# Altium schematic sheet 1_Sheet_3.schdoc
size 497 x 243 mm; Name: A_A4; Symbol: A_A4; Device: A_A4; @Project Name: RM_超级电容控制板; REV: 3.4; Date: 2023-02-08; Sheet: 3/3; Draw By: PKKKK; Company: QiDian; Convert to PCB: yes; Add into BOM: yes
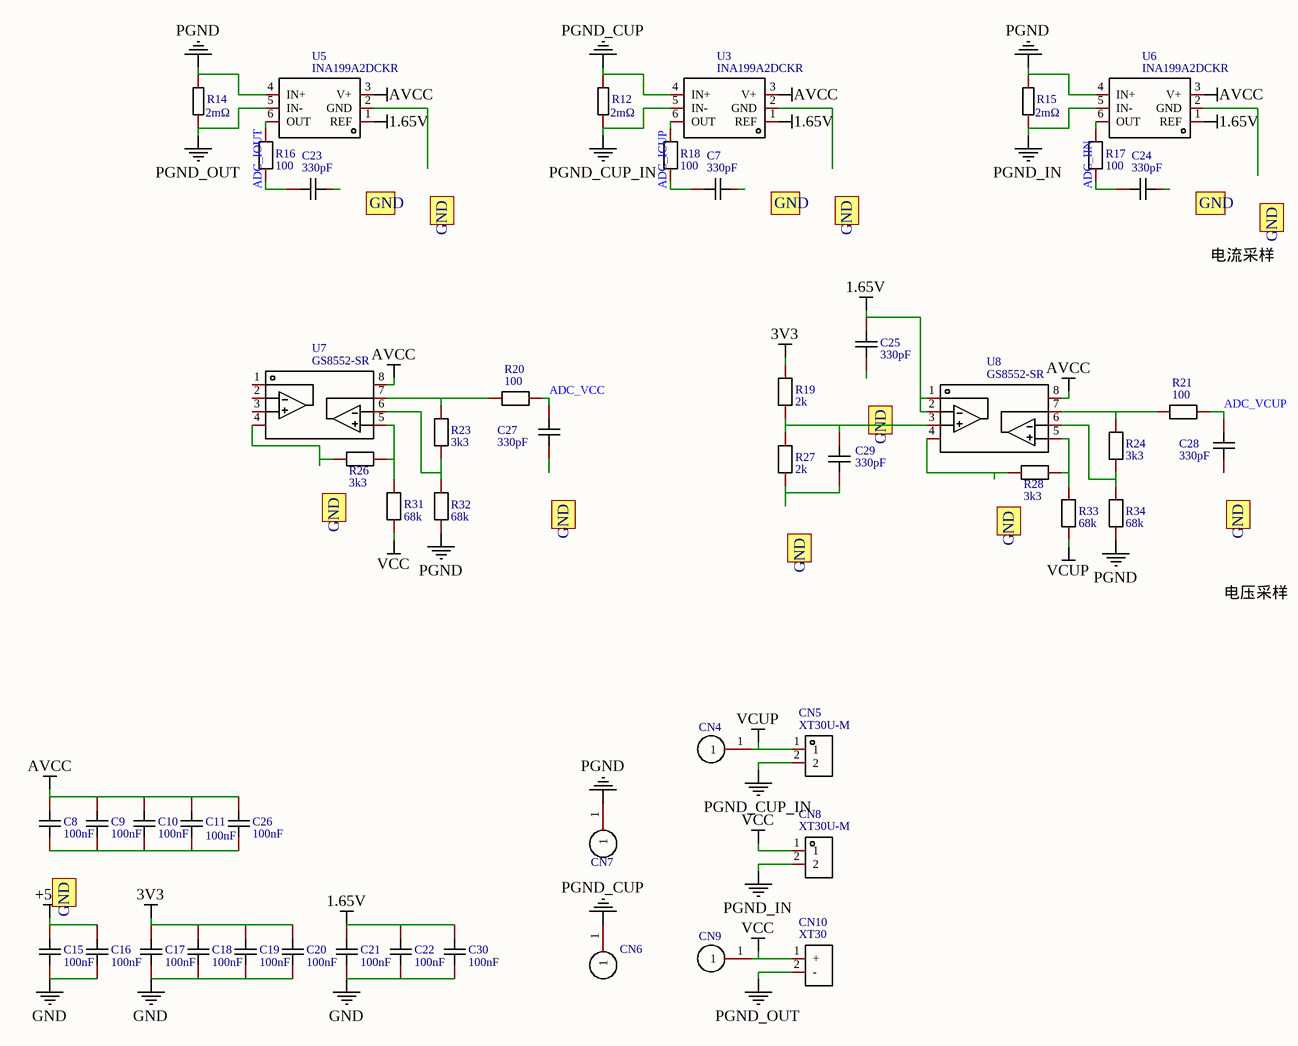
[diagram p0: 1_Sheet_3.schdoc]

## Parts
C7  330pF  [C0603]
C8  100nF  [C0603]
C9  100nF  [C0603]
C10  100nF  [C0603]
C11  100nF  [C0603]
C15  100nF  [C0603]
C16  100nF  [C0603]
C17  100nF  [C0603]
C18  100nF  [C0603]
C19  100nF  [C0603]
C20  100nF  [C0603]
C21  100nF  [C0603]
C22  100nF  [C0603]
C23  330pF  [C0603]
C24  330pF  [C0603]
C25  330pF  [C0603]
C26  100nF  [C0603]
C27  330pF  [C0603]
C28  330pF  [C0603]
C29  330pF  [C0603]
C30  100nF  [C0603]
CN4  m3焊盘  [M3焊盘]  (value not drawn)
CN5  XT30U-M  [CONN-TH_XT30U-M]
CN6  m3焊盘  [M3焊盘]  (value not drawn)
CN7  m3焊盘  [M3焊盘]  (value not drawn)
CN8  XT30U-M  [CONN-TH_XT30U-M]
CN9  m3焊盘  [M3焊盘]  (value not drawn)
CN10  XT30  [CONN-TH_XT30UPB-F]
R12  2mΩ  [R2512]
R14  2mΩ  [R2512]
R15  2mΩ  [R2512]
R16  100  [R0603]
R17  100  [R0603]
R18  100  [R0603]
R19  2k  [R0603]
R20  100  [R0603]
R21  100  [R0603]
R23  3k3  [R0603]
R24  3k3  [R0603]
R26  3k3  [R0603]
R27  2k  [R0603]
R28  3k3  [R0603]
R31  68k  [R0603]
R32  68k  [R0603]
R33  68k  [R0603]
R34  68k  [R0603]
U3  INA199A2DCKR  [SOT-363_L2.0-W1.3-P0.65-LS2.1-BR]
U5  INA199A2DCKR  [SOT-363_L2.0-W1.3-P0.65-LS2.1-BR]
U6  INA199A2DCKR  [SOT-363_L2.0-W1.3-P0.65-LS2.1-BR]
U7  GS8552-SR  [SOIC-8_L5.0-W4.0-P1.27-LS6.0-BL]
U8  GS8552-SR  [SOIC-8_L5.0-W4.0-P1.27-LS6.0-BL]

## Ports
GND (out)

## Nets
1.65V: C21.2 C22.2 C25.1 C30.2 U3.1(REF) U5.1(REF) U6.1(REF) U8.1(OUTA) U8.2(INA-)
3V3: C17.2 C18.2 C19.2 C20.2 R19.1
+5V: C15.2 C16.2
AVCC: C8.2 C9.2 C10.2 C11.2 C26.2 U3.3(V+) U5.3(V+) U6.3(V+) U7.8(VDD) U8.8(VDD)
GND: C15.1 C16.1 C17.1 C18.1 C19.1 C20.1 C21.1 C22.1 C30.1
PGND: CN7.1 R14.1 R15.1 R32.2 R34.1 U5.4(IN+) U6.4(IN+)
PGND_CUP: CN6.1 R12.1 U3.4(IN+)
PGND_CUP_IN: CN5.2 R12.2 U3.5(IN-)
PGND_IN: CN8.2 R15.2 U6.5(IN-)
PGND_OUT: CN10.2(-) R14.2 U5.5(IN-)
VCC: CN8.1 CN9.1 CN10.1(+) R31.1
VCUP: CN4.1 CN5.1 R33.1
ADC_ICUP: C7.2 R18.1
ADC_IIN: C24.2 R17.1
ADC_IOUT: C23.2 R16.1
ADC_VCC: C27.2 R20.1
ADC_VCUP: C28.2 R21.1
NetC8_1: C8.1 C9.1 C10.1 C11.1 C26.1
NetC29_1: C29.1 R27.2
NetC29_2: C29.2 R19.2 R27.1 U8.3(INA+)
NetR16_2: R16.2 U5.6(OUT)
NetR17_2: R17.2 U6.6(OUT)
NetR18_2: R18.2 U3.6(OUT)
NetR20_2: R20.2 R23.1 U7.7(OUTB)
NetR21_2: R21.2 R24.1 U8.7(OUTB)
NetR23_2: R23.2 R32.1 U7.6(INB-)
NetR24_2: R24.2 R34.2 U8.6(INB-)
NetR26_1: R26.1 U7.4(VSS)
NetR26_2: R26.2 R31.2 U7.5(INB+)
NetR28_1: R28.1 U8.4(VSS)
NetR28_2: R28.2 R33.2 U8.5(INB+)

Not connected (* = marked no-connect by the designer): C7 1; C23 1; C24 1; C25 2; C27 1; C28 1; U3 2(GND); U5 2(GND); U6 2(GND); U7 1(OUTA) 2(INA-) 3(INA+)

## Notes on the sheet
- 电流采样
- 电压采样

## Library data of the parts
C7 C23-C25 C27-C29 = 330pF: 3DModel: C0603_L1.6-W0.8-H0.8; Add into BOM: yes
C8-C11 C15-C22 C26 C30 = 0.1u: Symbol: 100n; 3DModel: C0603_L1.6-W0.8-H0.8; Add into BOM: yes
CN4 CN6 CN7 CN9 = m3焊盘: Add into BOM: yes
CN5 CN8 = XT30U-M: Manufacturer: AMASS(艾迈斯); Add into BOM: yes
CN10 = XT30: Manufacturer: Changzhou Amass Elec; Manufacturer Part: XT30UPB-F; Add into BOM: yes
R12 R14 R15 = 2mΩ: Manufacturer: Ever Ohms Tech; Manufacturer Part: MA251230FR005MZ; 3DModel: R2512_L6.3-W3.2-H0.6; Resistance: 0.005; Add into BOM: yes
R16-R18 R20 R21 = 100: Add into BOM: yes
R19 R27 = 2k: Add into BOM: yes
R23 R24 R26 R28 = 3k3: Add into BOM: yes
R31-R34 = 68k: Add into BOM: yes
U3 U5 U6 = INA199A2DCKR: Manufacturer: TI(德州仪器); 3DModel: SOT-363-6P_L2.0-W1.3-H1.1-LS2.0-P0.65; Add into BOM: yes
U7 U8 = GS8552-SR: Manufacturer: Gainsil; 3DModel: SOIC-8_L4.9-W3.9-H1.7-LS6.0-P1.27; Add into BOM: yes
